// Mitsubishi GX Works2 project: MC-38MR-8MTS-F700-H3G-4C   PLC: FX3G

PROGRAM MAIN
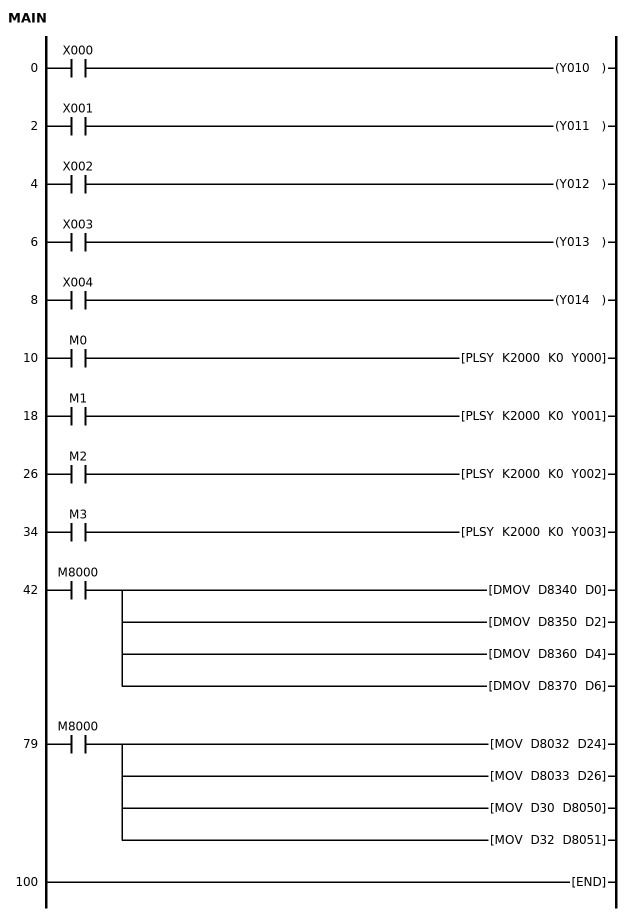
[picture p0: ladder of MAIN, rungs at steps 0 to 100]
0     LD      X000
      OUT     Y010
2     LD      X001
      OUT     Y011
4     LD      X002
      OUT     Y012
6     LD      X003
      OUT     Y013
8     LD      X004
      OUT     Y014
10    LD      M0
      PLSY    K2000 K0 Y000
18    LD      M1
      PLSY    K2000 K0 Y001
26    LD      M2
      PLSY    K2000 K0 Y002
34    LD      M3
      PLSY    K2000 K0 Y003
42    LD      M8000
      DMOV    D8340 D0
      DMOV    D8350 D2
      DMOV    D8360 D4
      DMOV    D8370 D6
79    LD      M8000
      MOV     D8032 D24
      MOV     D8033 D26
      MOV     D30 D8050
      MOV     D32 D8051
100   END
END_PROGRAM
